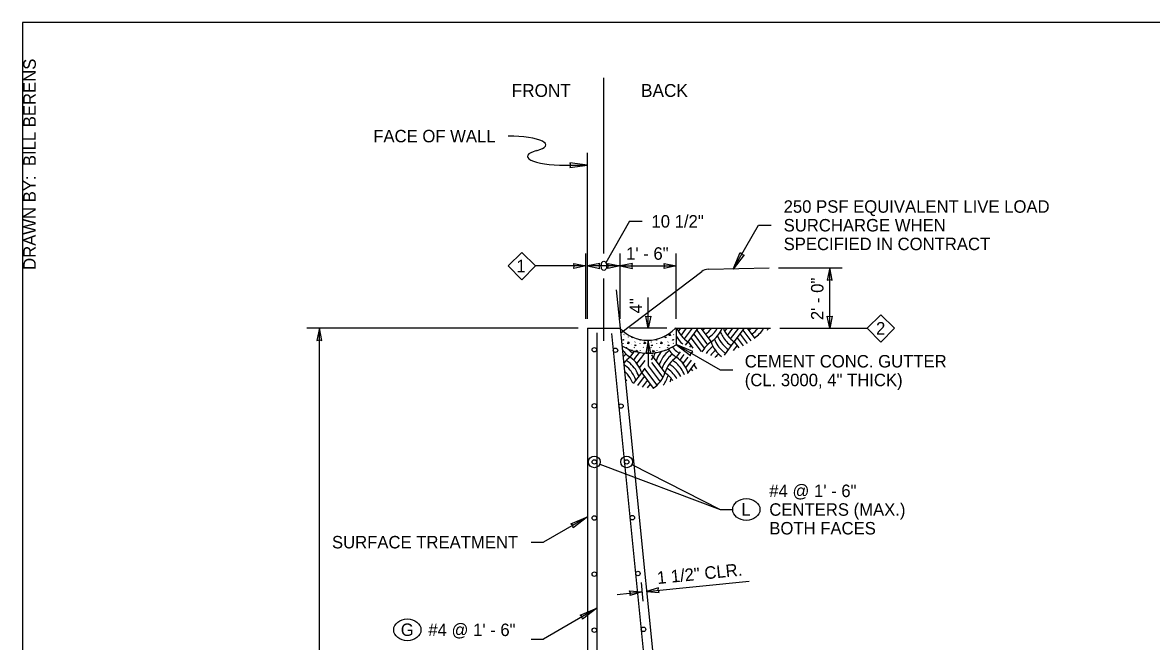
# Model space of a CAD drawing. Extents: x 99862 to 103151, y 100000 to 105076.
# Drawn here: x 99862 to 101311, y 101281 to 102076 of the extents above; entities that cross this region are included whole.
import ezdxf

# ---------------------------------------------------------------- set-up
doc = ezdxf.new("R2010")
doc.units = 0
for name, color, linetype in [('Level 1', 7, 'Continuous'), ('Level 10', 7, 'Continuous'), ('Level 13', 7, 'Continuous'), ('Level 15', 7, 'Continuous'), ('Level 2', 7, 'Continuous'), ('Level 20', 7, 'Continuous'), ('Level 22', 7, 'Continuous'), ('Level 5', 7, 'Continuous'), ('Level 62', 7, 'Continuous')]:
    doc.layers.add(name, color=color, linetype=linetype)

msp = doc.modelspace()

# ---------------------------------------------------------------- linework, layer by layer
at = {"layer": 'Level 1'}
msp.add_lwpolyline([(99862, 99999.5), (103151, 99999.5), (103151, 102075.5), (99862, 102075.5)], close=True, dxfattribs=at)
at = {"layer": 'Level 10'}
for p, q in [((100586.9, 101683.1), (100586.9, 100771.1)), ((100586.9, 101683.1), (100628.9, 101683.1)), ((100628.9, 101683.1), (100720.4, 100771.1)), ((100633.6, 101674.9), (100633.8, 101675.3)), ((100697.4, 101674.9), (100697.6, 101675.3)), ((100700.9, 101682.1), (100700.9, 101662.1)), ((100633.2, 101663.6), (100633.3, 101664)), ((100637.2, 101658.5), (100637.4, 101658.9)), ((100639.2, 101672.1), (100639.3, 101671.8)), ((100643.7, 101662.5), (100643.8, 101662.1)), ((100647.7, 101665.5), (100647.9, 101665.9)), ((100654.4, 101663.6), (100654.6, 101664)), ((100658.5, 101658.5), (100658.7, 101658.9)), ((100665, 101662.5), (100665, 101662.1)), ((100669, 101665.5), (100669.1, 101665.9)), ((100675.7, 101663.6), (100675.9, 101664)), ((100679.7, 101658.5), (100679.9, 101658.9)), ((100686.3, 101662.5), (100686.3, 101662.1)), ((100690.2, 101665.5), (100690.4, 101665.9)), ((100697, 101663.6), (100697.2, 101664)), ((100644.1, 101655.2), (100644.3, 101655.6)), ((100646.8, 101658.5), (100646.9, 101658.2)), ((100646.9, 101658.4), (100647.1, 101658.1)), ((100654.9, 101654.2), (100655.1, 101654.6)), ((100660.4, 101651.3), (100660.5, 101651.3)), ((100665.4, 101655.2), (100665.6, 101655.6)), ((100668, 101658.5), (100668.2, 101658.2)), ((100668.2, 101658.4), (100668.4, 101658.1)), ((100676.1, 101654.2), (100676.3, 101654.6)), ((100686.7, 101655.2), (100686.8, 101655.6)), ((100689.3, 101658.5), (100689.5, 101658.2)), ((100689.5, 101658.4), (100689.6, 101658.1))]:
    msp.add_line(p, q, dxfattribs=at)
for points in [[(100691.4, 101673.7), (100692.5, 101675.7)], [(100692.7, 101675.8), (100693.6, 101673.9), (100691.5, 101673.7)], [(100632.3, 101667.7), (100632.8, 101668.9), (100633.7, 101668.2), (100632.3, 101667.7)], [(100638.6, 101663.2), (100638.9, 101665.7), (100640.5, 101664.1), (100638.6, 101663.2)], [(100643.8, 101670.9), (100644.2, 101671.7)], [(100645.1, 101671.3), (100643.8, 101670.9)], [(100647.8, 101660.8), (100648.3, 101661.9), (100649.2, 101661.2), (100647.8, 101660.8)], [(100654.7, 101668.4), (100655, 101668.2), (100653.6, 101667.7)], [(100653.6, 101667.7), (100653.9, 101668.4)], [(100659.8, 101663.2), (100660.2, 101665.7), (100661.8, 101664.1), (100659.9, 101663.2)], [(100669, 101660.8), (100669.6, 101661.9), (100670.5, 101661.2), (100669, 101660.8)], [(100676, 101668.4), (100676.2, 101668.2), (100674.8, 101667.7)], [(100674.8, 101667.7), (100675, 101668.2)], [(100681.1, 101663.2), (100681.5, 101665.7), (100683, 101664.1), (100681.1, 101663.2)], [(100686.4, 101670.9), (100686.9, 101672), (100687.8, 101671.4), (100686.4, 101670.9)], [(100690.3, 101660.8), (100690.8, 101661.9), (100691.7, 101661.2), (100690.3, 101660.8)], [(100696.1, 101667.7), (100696.6, 101668.9), (100697.5, 101668.2), (100696.1, 101667.7)], [(100649, 101653.2), (100650.1, 101655.2), (100651, 101653.1), (100649.5, 101653)], [(100670.2, 101653), (100671.4, 101655.2), (100672.3, 101653.1), (100670.2, 101653)]]:
    msp.add_lwpolyline(points, dxfattribs=at)
for centre, radius, start, end in [((100664.2, 101716.3), 48.5, 223.301, 316.2231), ((100699.9, 101682.1), 1, 0, 134.9971), ((100664.9, 101715.6), 64.5, 238.4535, 303.9272)]:
    msp.add_arc(centre, radius, start, end, dxfattribs=at)
at = {"layer": 'Level 13'}
for p, q in [((100598.7, 101677.1), (100598.7, 100879.1)), ((100617.6, 101676.5), (100692.8, 100926.6))]:
    msp.add_line(p, q, dxfattribs=at)
at = {"layer": 'Level 15'}
for p, q in [((100607.9, 101779.1), (100607.9, 102004.4)), ((100586.9, 101695.1), (100586.9, 101908.4)), ((100558, 101892.4), (100586.9, 101892.4)), ((100641, 101820.4), (100610.3, 101767.3)), ((100641, 101820.4), (100657, 101820.4)), ((100774, 101759), (100806.5, 101815.3)), ((100806.5, 101815.3), (100822.5, 101815.3)), ((100584.9, 101695.1), (100584.9, 101779.1)), ((100628.9, 101695.1), (100628.9, 101779.1)), ((100700.9, 101695.1), (100700.9, 101779.1)), ((100584.9, 101763.1), (100520.1, 101763.1)), ((100628.9, 101763.1), (100586.9, 101763.1)), ((100628.9, 101763.1), (100700.9, 101763.1)), ((100831.9, 101760.7), (100913.7, 101760.7)), ((100897.7, 101683.1), (100897.7, 101760.7)), ((100607.9, 101667.1), (100607.9, 101747.1)), ((100623.9, 101732.4), (100628.9, 101683.1)), ((100664.9, 101683.1), (100664.9, 101722.8)), ((100574.9, 101683.1), (100226.9, 101683.1)), ((100242.9, 101195.1), (100242.9, 101683.1)), ((100688.9, 101683.1), (100640.9, 101683.1)), ((100703.7, 101679.2), (100706.6, 101683.1)), ((100707.1, 101673.9), (100714, 101683.1)), ((100711.2, 101669.4), (100721.5, 101683.1)), ((100715.9, 101665.7), (100728.9, 101683.1)), ((100723.3, 101675.6), (100736.8, 101657.6)), ((100727, 101680.6), (100740.9, 101662)), ((100732.5, 101683.1), (100745.6, 101665.7)), ((100763.1, 101679.2), (100766, 101683.1)), ((100766.5, 101673.9), (100773.4, 101683.1)), ((100770.6, 101669.4), (100780.9, 101683.1)), ((100775.3, 101665.7), (100788.3, 101683.1)), ((100782.7, 101675.6), (100791.6, 101663.8)), ((100786.4, 101680.6), (100796.6, 101667)), ((100791.9, 101683.1), (100801.6, 101670.2)), ((100833.7, 101683.1), (100945.7, 101683.1)), ((100664.9, 101667.1), (100664.9, 101635.1)), ((100700.9, 101662.1), (100757.2, 101629.6)), ((100712.7, 101661.5), (100715.9, 101665.7)), ((100715.9, 101665.7), (100721.9, 101657.7)), ((100718.4, 101659.1), (100719.6, 101660.8)), ((100719.6, 101670.7), (100732.7, 101653.2)), ((100762.6, 101648.8), (100775.3, 101665.7)), ((100774.4, 101654.6), (100779, 101660.8)), ((100775.3, 101665.7), (100781.1, 101658)), ((100779, 101670.7), (100786.5, 101660.7)), ((100641.6, 101645.9), (100647.7, 101654)), ((100646.3, 101642.2), (100649, 101645.9)), ((100649, 101645.9), (100653.9, 101652.4)), ((100650.4, 101637.8), (100656.5, 101645.9)), ((100656.5, 101645.9), (100660.5, 101651.2)), ((100668.9, 101649.2), (100671.3, 101645.9)), ((100668.9, 101642.7), (100671.3, 101645.9)), ((100671.3, 101645.9), (100686.2, 101626.1)), ((100674, 101652.3), (100674, 101652.3)), ((100701, 101645.9), (100706.3, 101652.9)), ((100705.7, 101642.2), (100708.4, 101645.9)), ((100708.4, 101645.9), (100711, 101649.3)), ((100709.7, 101637.8), (100715.9, 101645.9)), ((100653.8, 101632.5), (100660.9, 101641.9)), ((100656.5, 101626.1), (100660.9, 101632)), ((100660.2, 101631.1), (100676, 101610)), ((100664.6, 101635.1), (100680, 101614.5)), ((100668.9, 101639.3), (100683.5, 101619.8)), ((100713.2, 101632.5), (100720.4, 101642.1)), ((100715.9, 101626.1), (100725.1, 101638.5)), ((100719.6, 101631.1), (100721.5, 101628.5)), ((100723.3, 101636), (100726.9, 101631.2)), ((100646, 101612.1), (100656.5, 101626.1)), ((100651.7, 101609.9), (100660.2, 101621.2)), ((100656.5, 101626.1), (100671.3, 101606.3)), ((100657.5, 101607.7), (100663.9, 101616.2)), ((100715.4, 101625.5), (100715.9, 101626.1)), ((100715.9, 101626.1), (100716.1, 101625.8)), ((100757.2, 101629.6), (100773.2, 101629.6)), ((100664.1, 101606.6), (100667.6, 101611.3)), ((100671.2, 101606.1), (100671.3, 101606.3)), ((100671.3, 101606.3), (100671.4, 101606.2)), ((100602.8, 101508.9), (100757.2, 101450.5)), ((100643.9, 101508.2), (100757.2, 101450.5)), ((100757.2, 101450.5), (100773.2, 101450.5)), ((100586.9, 101441.1), (100530.6, 101408.6)), ((100514.6, 101408.6), (100530.6, 101408.6)), ((100655.6, 101356.7), (100658, 101332.8)), ((100662.8, 101345.4), (100794.4, 101358.6)), ((100625, 101341.6), (100656.8, 101344.8)), ((100598.7, 101323.7), (100530.6, 101284.3)), ((100514.6, 101284.3), (100530.6, 101284.3))]:
    msp.add_line(p, q, dxfattribs=at)
for points in [[(100586.9, 101892.4), (100564.1, 101895.4), (100565.1, 101892.4), (100564.1, 101889.4)], [(100774, 101759), (100782.9, 101780.2), (100784.9, 101777.8), (100788, 101777.3)], [(100584.9, 101763.1), (100569.2, 101760), (100569.9, 101763.1), (100569.2, 101766.2)], [(100586.9, 101763.1), (100602.6, 101760), (100601.9, 101763.1), (100602.6, 101766.2)], [(100628.9, 101763.1), (100613.2, 101760), (100613.9, 101763.1), (100613.2, 101766.2)], [(100628.9, 101763.1), (100644.6, 101760), (100643.9, 101763.1), (100644.6, 101766.2)], [(100700.9, 101763.1), (100685.2, 101760), (100685.9, 101763.1), (100685.2, 101766.2)], [(100897.7, 101760.7), (100894.6, 101745), (100897.7, 101745.7), (100900.7, 101745)], [(100664.9, 101683.1), (100661.8, 101698.8), (100664.9, 101698.1), (100668, 101698.8)], [(100897.7, 101683.1), (100894.6, 101698.8), (100897.7, 101698.1), (100900.7, 101698.8)], [(100242.9, 101683.1), (100239.8, 101667.4), (100242.9, 101668.1), (100246, 101667.4)], [(100664.9, 101667.1), (100661.8, 101651.4), (100664.9, 101652.1), (100668, 101651.4)], [(100700.9, 101662.1), (100719.2, 101648.1), (100719.7, 101651.2), (100722.1, 101653.2)], [(100586.9, 101441.1), (100568.6, 101427.1), (100568, 101430.2), (100565.6, 101432.3)], [(100656.8, 101344.8), (100641.5, 101340.1), (100641.9, 101343.3), (100640.8, 101346.3)], [(100662.8, 101345.4), (100678.7, 101343.9), (100677.7, 101346.9), (100678.1, 101350)], [(100598.7, 101323.7), (100580.5, 101309.7), (100579.9, 101312.8), (100577.5, 101314.8)]]:
    msp.add_lwpolyline(points, close=True, dxfattribs=at)
for centre in [(100595.7, 101511.6), (100637.2, 101511.6)]:
    msp.add_circle(centre, 7.5, dxfattribs=at)
for centre, start, end in [((100736.8, 101696.9), 201.5684, 236.0964), ((100713.5, 101711.8), 303.9036, 310.2904), ((100717.2, 101706.8), 303.9036, 320.872), ((100720.9, 101701.9), 303.9036, 330.0441), ((100724.6, 101696.9), 303.9036, 338.4316), ((100792.5, 101692), 200.8778, 211.332), ((100796.2, 101696.9), 201.5684, 236.0964), ((100772.9, 101711.8), 303.9036, 310.2904), ((100776.6, 101706.8), 303.9036, 320.872), ((100780.3, 101701.9), 303.9036, 330.0441), ((100784, 101696.9), 334.4077, 338.4316), ((100855.6, 101696.9), 201.5684, 202.3888), ((100725.7, 101682.1), 216.8955, 228.9599), ((100733.1, 101692), 210.9479, 211.332), ((100729.4, 101687), 220.6376, 220.9416), ((100733.1, 101692), 211.3319, 230.566), ((100766.5, 101634.5), 123.9036, 150.9316), ((100770.2, 101629.6), 126.3063, 146.0717), ((100781.4, 101677.1), 197.6434, 233.2817), ((100785.1, 101682.1), 200.2432, 228.9599), ((100788.8, 101687), 201.4344, 220.9416), ((100792.5, 101692), 211.3319, 236.0964), ((100788.8, 101687), 220.9415, 236.0964), ((100662.6, 101677.1), 214.5366, 236.0964), ((100655.2, 101624.6), 127.1006, 128.4292), ((100658.9, 101619.7), 126.331, 134.4399), ((100662.6, 101614.7), 123.9036, 141.0075), ((100666.3, 101682.1), 221.9566, 228.9599), ((100666.3, 101682.1), 228.9599, 236.0964), ((100620.7, 101614.7), 17.6434, 56.0963), ((100707.1, 101634.5), 151.8027, 162.3566), ((100710.8, 101629.6), 154.2265, 162.3566), ((100710.8, 101629.6), 139.8725, 154.2266), ((100714.6, 101624.6), 145.491, 162.3566), ((100718.3, 101619.7), 135.7127, 162.3566), ((100714.6, 101624.6), 127.1006, 145.4911), ((100722, 101614.7), 123.9036, 162.3566), ((100722, 101677.1), 212.5653, 236.0964), ((100718.3, 101619.7), 126.331, 135.7128), ((100725.7, 101682.1), 228.9599, 236.0964), ((100680.1, 101614.7), 17.6434, 56.0963), ((100774, 101624.6), 127.1006, 141.1271), ((100777.7, 101619.7), 135.7127, 136.0523), ((100777.7, 101619.7), 126.331, 135.7128), ((100785.1, 101682.1), 228.9599, 236.0964), ((100613.2, 101604.8), 40.9413, 57.2389), ((100616.9, 101609.8), 48.9597, 58.5465), ((100616.9, 101609.8), 17.6434, 48.9597), ((100668.9, 101599.9), 31.3316, 58.4874), ((100672.6, 101604.8), 40.9413, 59.3021), ((100676.3, 101609.8), 48.9597, 58.5465), ((100676.3, 101609.8), 21.3725, 48.9597), ((100609.5, 101599.9), 31.3316, 48.5208), ((100605.8, 101594.9), 33.1226, 38.0276), ((100613.2, 101604.8), 17.6434, 40.9414), ((100609.5, 101599.9), 19.6766, 31.3317), ((100650.4, 101637.5), 303.9036, 342.3566), ((100654.1, 101632.6), 323.1761, 345.0113), ((100665.2, 101594.9), 34.176, 56.0964), ((100657.8, 101627.6), 339.4032, 346.3199), ((100672.6, 101604.8), 25.6363, 40.9414), ((100668.9, 101599.9), 29.8965, 31.3317)]:
    msp.add_arc(centre, 37.6, start, end, dxfattribs=at)
for centre, start_param, end_param in [((100485.2, 101918.5), 5.569461, 7.853982), ((100558, 101903.7), 2.427868, 4.712389)]:
    msp.add_ellipse(centre, major_axis=(48.2, 0), ratio=0.234933, start_param=start_param, end_param=end_param, dxfattribs=at)
msp.add_ellipse((100607.9, 101763.1), major_axis=(0, -6), ratio=0.57735, dxfattribs=at)
at = {"layer": 'Level 2'}
msp.add_line((100699.9, 101683.1), (100821.7, 101683.1), dxfattribs=at)
at = {"layer": 'Level 20'}
for points in [[(100502.5, 101780.6), (100520.1, 101763.1), (100502.5, 101745.5), (100485, 101763.1)], [(100963.2, 101700.6), (100980.8, 101683.1), (100963.2, 101665.5), (100945.7, 101683.1)]]:
    msp.add_lwpolyline(points, close=True, dxfattribs=at)
for centre in [(100790.7, 101450.5), (100355.7, 101296.1)]:
    msp.add_ellipse(centre, major_axis=(-17.5, 0), ratio=0.8, dxfattribs=at)
at = {"layer": 'Level 22'}
for centre in [(100595.7, 101655.6), (100622.8, 101654.9), (100595.7, 101583.6), (100630, 101583.3), (100595.7, 101511.6), (100637.2, 101511.6), (100595.7, 101439.6), (100644.4, 101440), (100595.7, 101367.6), (100651.6, 101368.4), (100595.7, 101295.6), (100658.8, 101296.7)]:
    msp.add_circle(centre, 2.85, dxfattribs=at)
at = {"layer": 'Level 5'}
for p, q in [((100742, 101759), (100819.9, 101760.7)), ((100629.5, 101677.2), (100733.6, 101756.1))]:
    msp.add_line(p, q, dxfattribs=at)
msp.add_arc((100742.3, 101744.5), 14.5, 91.2659, 127.1192, dxfattribs=at)

# ---------------------------------------------------------------- texts
at = {"layer": 'Level 15'}
msp.add_text('1 1/2" CLR.', height=16, rotation=5.7293, dxfattribs=at).set_placement((100676.9, 101354.8))
at = {"layer": 'Level 20'}
for s, height, p in [('FRONT', 16.5, (100489.6, 101980.1)), ('BACK', 16.5, (100655.6, 101980.1)), ('250 PSF EQUIVALENT LIVE LOAD', 16, (100838.6, 101831.4)), ('10 1/2"', 16, (100669, 101812.4)), ('SURCHARGE WHEN', 16, (100838.6, 101807.4)), ('SPECIFIED IN CONTRACT', 16, (100838.6, 101783.4)), ('1\' - 6"', 16, (100636.5, 101771.1)), ('1', 16, (100495.6, 101755.1)), ('2', 16, (100957.2, 101675.1)), ('CEMENT CONC. GUTTER', 16, (100788.7, 101632.8)), ('(CL. 3000, 4" THICK)', 16, (100788.7, 101608.8)), ('#4 @ 1\' - 6"', 16, (100820.2, 101466.5)), ('L', 16, (100784.3, 101442.7)), ('CENTERS (MAX.)', 16, (100820.2, 101442.5)), ('BOTH FACES', 16, (100820.2, 101418.5)), ('SURFACE TREATMENT', 16, (100259, 101400.6)), ('G', 16, (100347.3, 101288.2)), ('  #4 @ 1\' - 6"', 16, (100370.8, 101288.1))]:
    msp.add_text(s, height=height, dxfattribs=at).set_placement(p)
for s, rotation, p in [('FACE OF WALL', 360, (100312, 101921.8)), ('2\' - 0"', 90, (100889.7, 101693.6)), ('4"', 90, (100656.9, 101702.2))]:
    msp.add_text(s, height=16, rotation=rotation, dxfattribs=at).set_placement(p)
at = {"layer": 'Level 62'}
msp.add_text('DRAWN BY:  BILL BERENS', height=16, rotation=90, dxfattribs=at).set_placement((99879, 101758.1))

doc.saveas('drawing.dxf')
